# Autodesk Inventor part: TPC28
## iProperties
Shininess: 64.0
Length Units: 11272
Angle Units: 11279
Time Units: 11290
Mass Units: 11286
Length Display Precision: 3
Angle Display Precision: 2
Compacted: True
Part Number: TPC28
Document SubType Name: Modeling
Created: 2004-08
Designer: Lori
Manufacturer: Standard
Standards Organization: Custom
Material: Steel, Mild
Density: 0.0
Volumn: 0.0
Area: 0.0
PropertySet Name: Model Information
Control State: 0
Master: False
Checked Out: False
Author: Lori
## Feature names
1. Base1
